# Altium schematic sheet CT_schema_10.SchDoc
size 209 x 185 mm
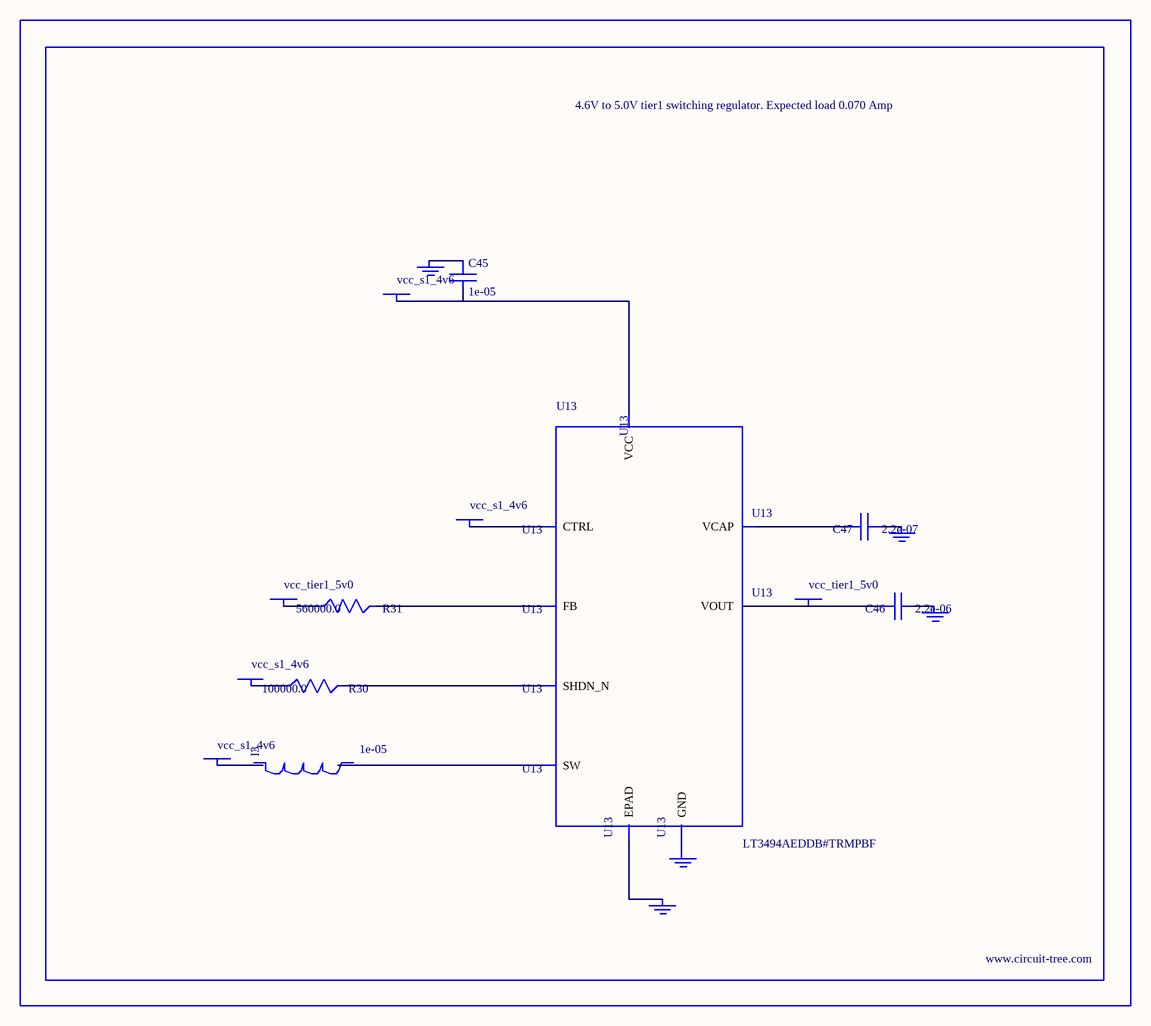
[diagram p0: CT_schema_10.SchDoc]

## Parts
BORDER9  (no value)
C45  1e-05  [C1210]
C46  2.2e-06  [C0603]
C47  2.2e-07  [C0603]
GND_INSTANCE_9_0  (no value)
GND_INSTANCE_9_1  (no value)
GND_INSTANCE_9_2  (no value)
GND_INSTANCE_9_3  (no value)
GND_INSTANCE_9_4  (no value)
I3  1e-05  [L1210]
POWER_INSTANCE_9_0  vcc_s1_4v6
POWER_INSTANCE_9_1  vcc_s1_4v6
POWER_INSTANCE_9_2  vcc_s1_4v6
POWER_INSTANCE_9_3  vcc_s1_4v6
POWER_INSTANCE_9_4  vcc_tier1_5v0
POWER_INSTANCE_9_5  vcc_tier1_5v0
R30  100000.0  [R0603]
R31  560000.0  [R0603]
U13  LT3494AEDDB#TRMPBF  [DFN-8_DDB]

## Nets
NetC45_1: C45.1 GND_INSTANCE_9_0.0(GND)
NetC45_2: C45.2 POWER_INSTANCE_9_1.0(PWR) U13.3(VCC)
NetC46_1: C46.1 GND_INSTANCE_9_1.0(GND)
NetC46_2: C46.2 POWER_INSTANCE_9_5.0(PWR) U13.7(VOUT)
NetC47_1: C47.1 GND_INSTANCE_9_2.0(GND)
NetC47_2: C47.2 U13.8(VCAP)
NetGND_INSTANCE_9_3_0: GND_INSTANCE_9_3.0(GND) U13.9(EPAD)
NetGND_INSTANCE_9_4_0: GND_INSTANCE_9_4.0(GND) U13.2(GND)
NetPOWER_INSTANCE_9_2_0: POWER_INSTANCE_9_2.0(PWR) U13.4(CTRL)
NetPOWER_INSTANCE_9_3_0: POWER_INSTANCE_9_3.0(PWR) R30.1
NetPOWER_INSTANCE_9_4_0: POWER_INSTANCE_9_4.0(PWR) R31.1
NetR30_2: R30.2 U13.5(SHDN_N)
NetR31_2: R31.2 U13.6(FB)

Not connected (* = marked no-connect by the designer): I3 1 2; POWER_INSTANCE_9_0 0(PWR); U13 1(SW)

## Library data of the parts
BORDER9 = BORDER_PAGE9
C45 = C1210C106K5PACTU
C46 = GRM188R61H225KE1115D
C47 = C0603C224K3RAC
GND_INSTANCE_9_0-GND_INSTANCE_9_4 = GND
I3 = CBC3225T100MR
POWER_INSTANCE_9_0-POWER_INSTANCE_9_5 = PWR
R30 = RC0603JR-07100KL
R31 = RC0603JR-07560KL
